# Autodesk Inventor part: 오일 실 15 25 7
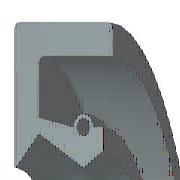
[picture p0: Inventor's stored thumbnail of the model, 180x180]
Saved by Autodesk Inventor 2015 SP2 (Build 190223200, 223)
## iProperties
Created: 2012-02
Part Number: 오일 실 15 25 7
Material: 고무
Description: 오일-실
Document SubType Name: Modeling
Standard: KS B 2804
Designer: mduedu
Standards Organization: KS
Language: ko-KR
Size Designation: D - 15 25 7
Categories: <MemberInstance><Categories><Category DisplayName="샤프트 부품" InternalName="7f7aeb1f-a693-4053-b835-cee3144e0d98" Mnemonic="SHFT"><Category DisplayName="실링" Intern
Density: 0.93 g/cm^3
Appearance: 고무 - 검은색 - 버전 1.1
IsCustomPart: 1
Author: mduedu
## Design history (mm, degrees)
revolve "본체" stored, may be unused: angle "d17" = 90 deg
revolve "스프링1" stored, may be unused: angle "d18" = 90 deg
body "Solid1"
sketch "스케치1"
  geometry: L1 (0, 12.5)-(7, 12.5); L2 (7, 10.75)-(1.75, 10.75); L3 (1.75, 9.25)-(4.9, 7.5); L4 (4.9, 7.5)-(0, 7.5); L5 (0, 0)-(9.586, 0) reference; L6 (4.9, 7.5)-(6.3, 8.375); L7 (0, 18)-(0, -3) reference; L8 (-1.941, 0)-(11.507, 0) reference; L9 (4.2, 9.6)-(1.75, 10.09); L10 (1.75, 10.09)-(1.75, 10.75); L11 (0, 12.5)-(0, 7.588); L12 (4.9, 7.5)-(0, 7.5); L13 (1.75, 9.25)-(0.152, 7.528); L14 (7, 12.5)-(7, 10.75); L15 (5.6, 9.6)-(6.3, 9.6); L16 (6.3, 9.6)-(6.3, 8.375); C1 r 0.455 at (4.9, 9.6); A1 r 0.7 centre (4.9, 9.6) between (5.6, 9.6) and (4.2, 9.6); A2 r 0.088 centre (0.088, 7.588) between (0, 7.588) and (0.152, 7.528); 1 further point
  constraints: 28 end point, 5 horizontal alignment, 5 point on line, 4 point on circle, 4 vertical alignment, 3 centre point, 3 tangent, 2 collinear, 2 horizontal, 2 perpendicular, 1 coincident, 1 parallel
  dimensions: "d0" = 25 diameter of L1 L5 (= SD2); "d1" = 1.75 distance of L1.end L2.start (= SD); "d2" = 0.91 diameter of C1 (= SPDI); "d3" = 1.4 diameter of A1 (= SPDA); "d4" = 15 diameter of L3.end L5 (= NND); "d5" = 18.5 diameter of L3.start L5 (= TKDM); "d7" = 20.18 diameter of L9.end L5 (= TKDM + 0.24 x SWDT); "d8" = 1.75 distance between parallel lines of L11 L10 (= SD); "d9" = 4.9 distance from line of L11 C1.centre (= SPDST); "d10" = 19.2 diameter of C1.centre L5 (= HLDM); "d11" = 0.0875 radius of A2 (= 0.25 x LAB); "d12" = 6.3 distance between parallel lines of L11 L16 (= SDI); "d13" = 16.75 diameter of L6.end L5 (= ABDM); "d14" = 7 distance from line of L11 L1.end (= SWDT)
fillet "모깎기1" dims "d6" = 0.3 (= RR)
other parameters: "SD2" = 25 [user parameter; used in 1 equation term], "SWDT" = 7 [user parameter; used in 2 equation terms], "RR" = 0.3 [user parameter; used in 1 equation term], "SD" = 1.75 [user parameter; used in 2 equation terms], "NND" = 15 [user parameter; used in 1 equation term], "SPDA" = 1.4 [user parameter; used in 1 equation term], "SPDI" = 0.91 [user parameter; used in 1 equation term], "TKDM" = 18.5 [user parameter; used in 2 equation terms], "HLDM" = 19.2 [user parameter; used in 1 equation term], "ABDM" = 16.75 [user parameter; used in 1 equation term], "SDI" = 6.3 [user parameter; used in 1 equation term], "SPDST" = 4.9 [user parameter; used in 1 equation term], "LAB" = 0.35 [user parameter; used in 1 equation term], "d15" = 0, "d16" = 0, "d19" = 0
